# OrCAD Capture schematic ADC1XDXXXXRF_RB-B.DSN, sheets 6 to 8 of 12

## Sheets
6 Power1: size C; block B4
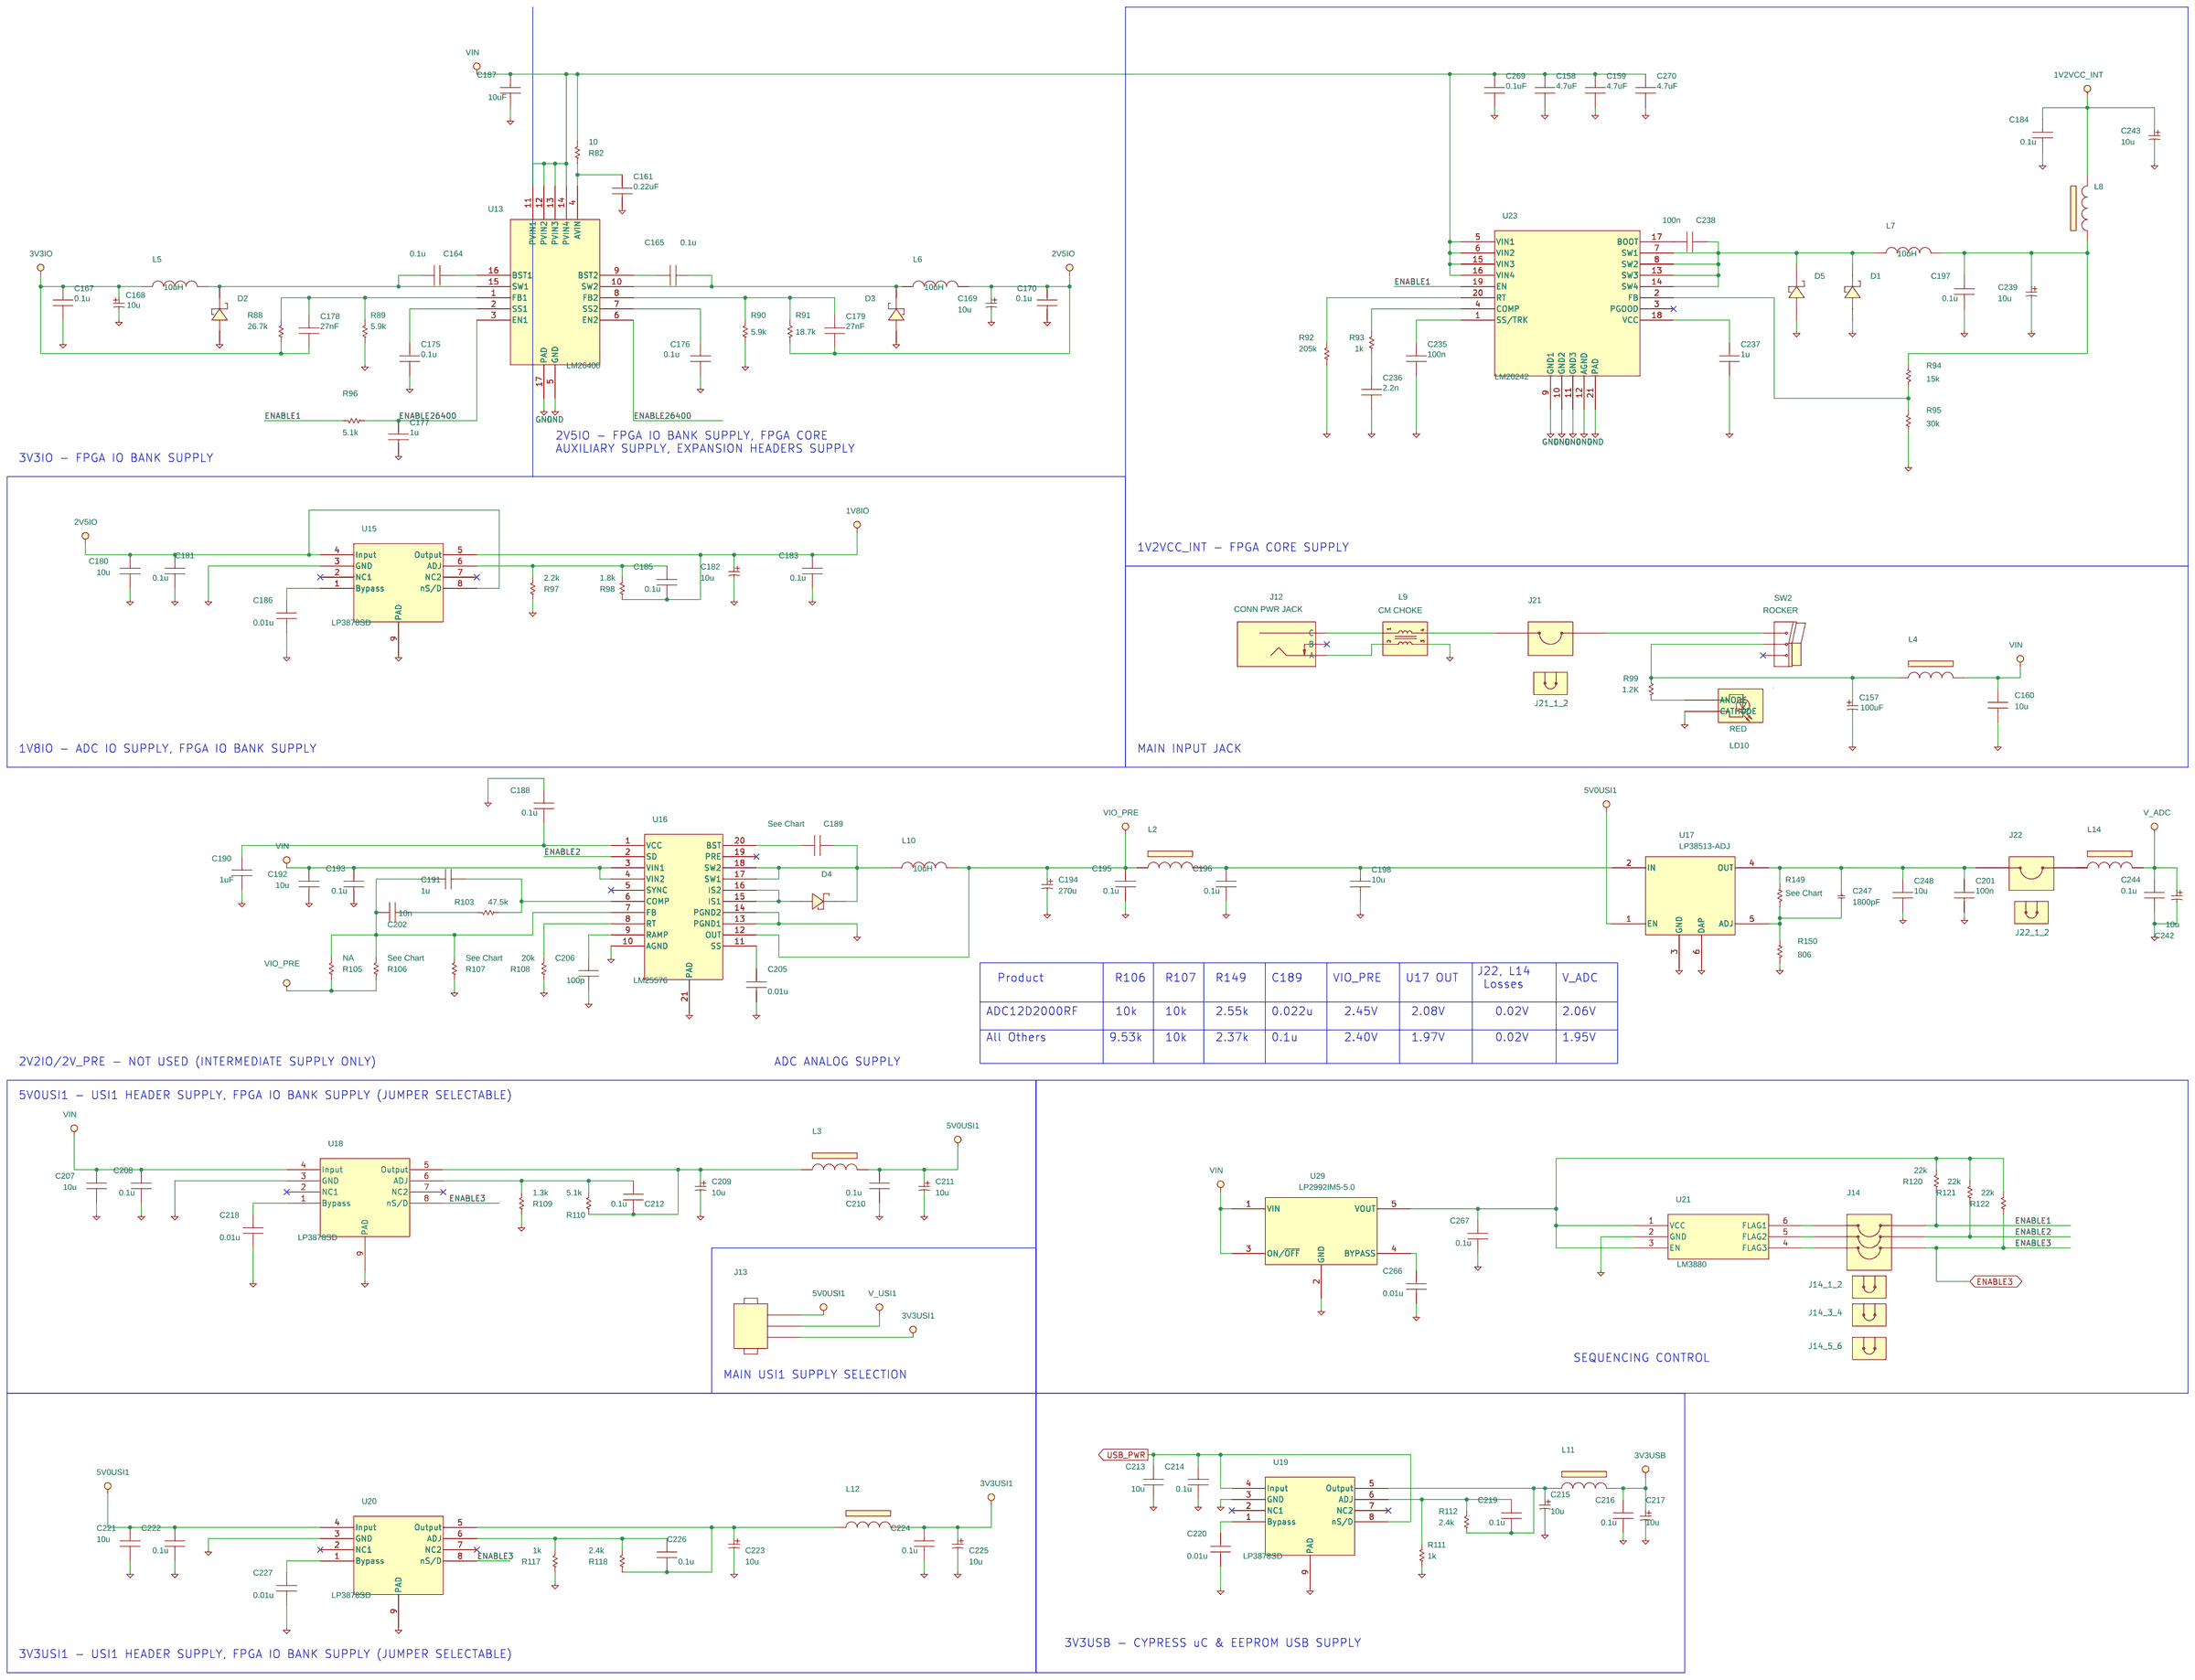
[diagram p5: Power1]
7 Power2: size C; block B4
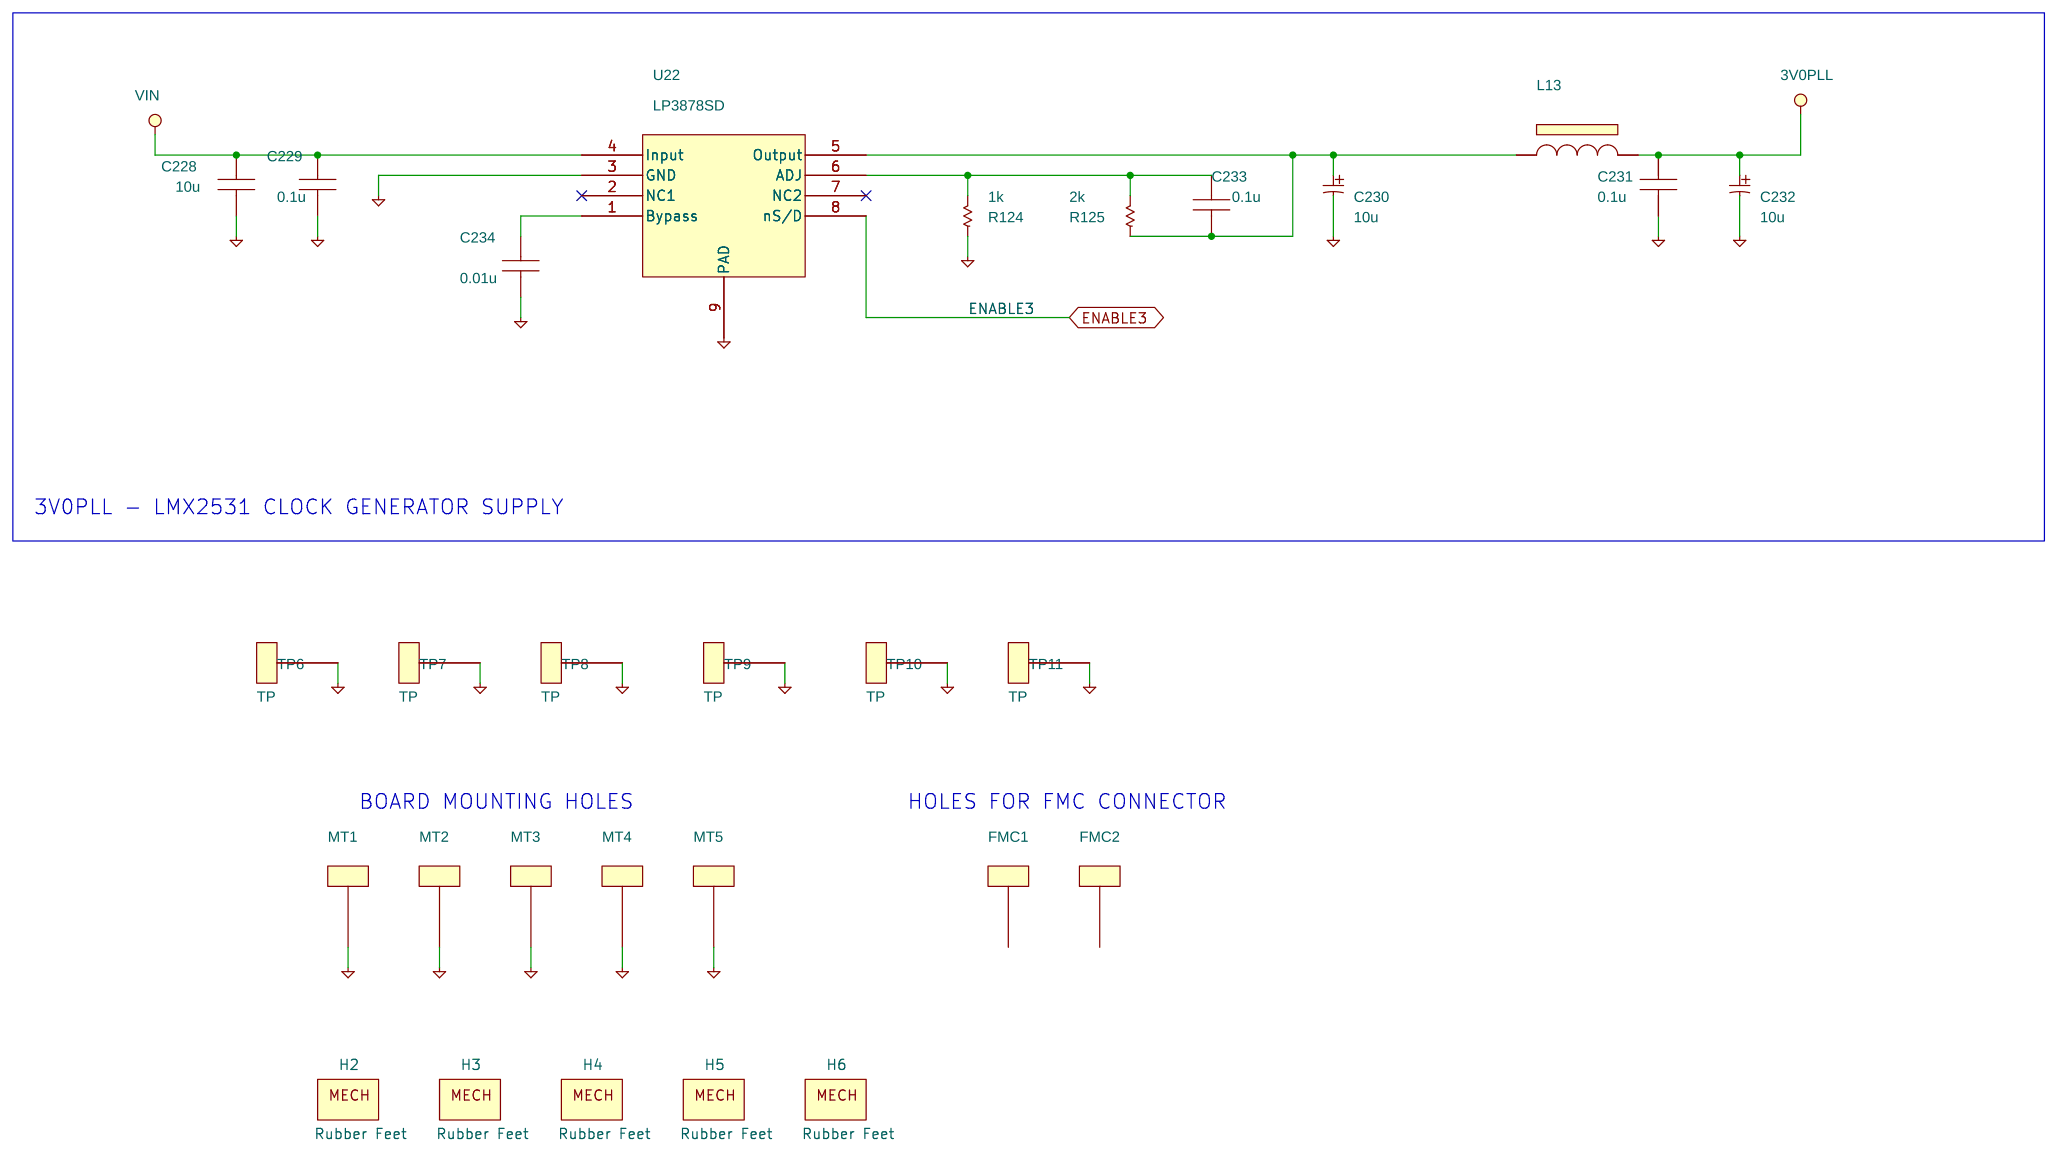
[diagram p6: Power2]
8 PLL: size C; block B3
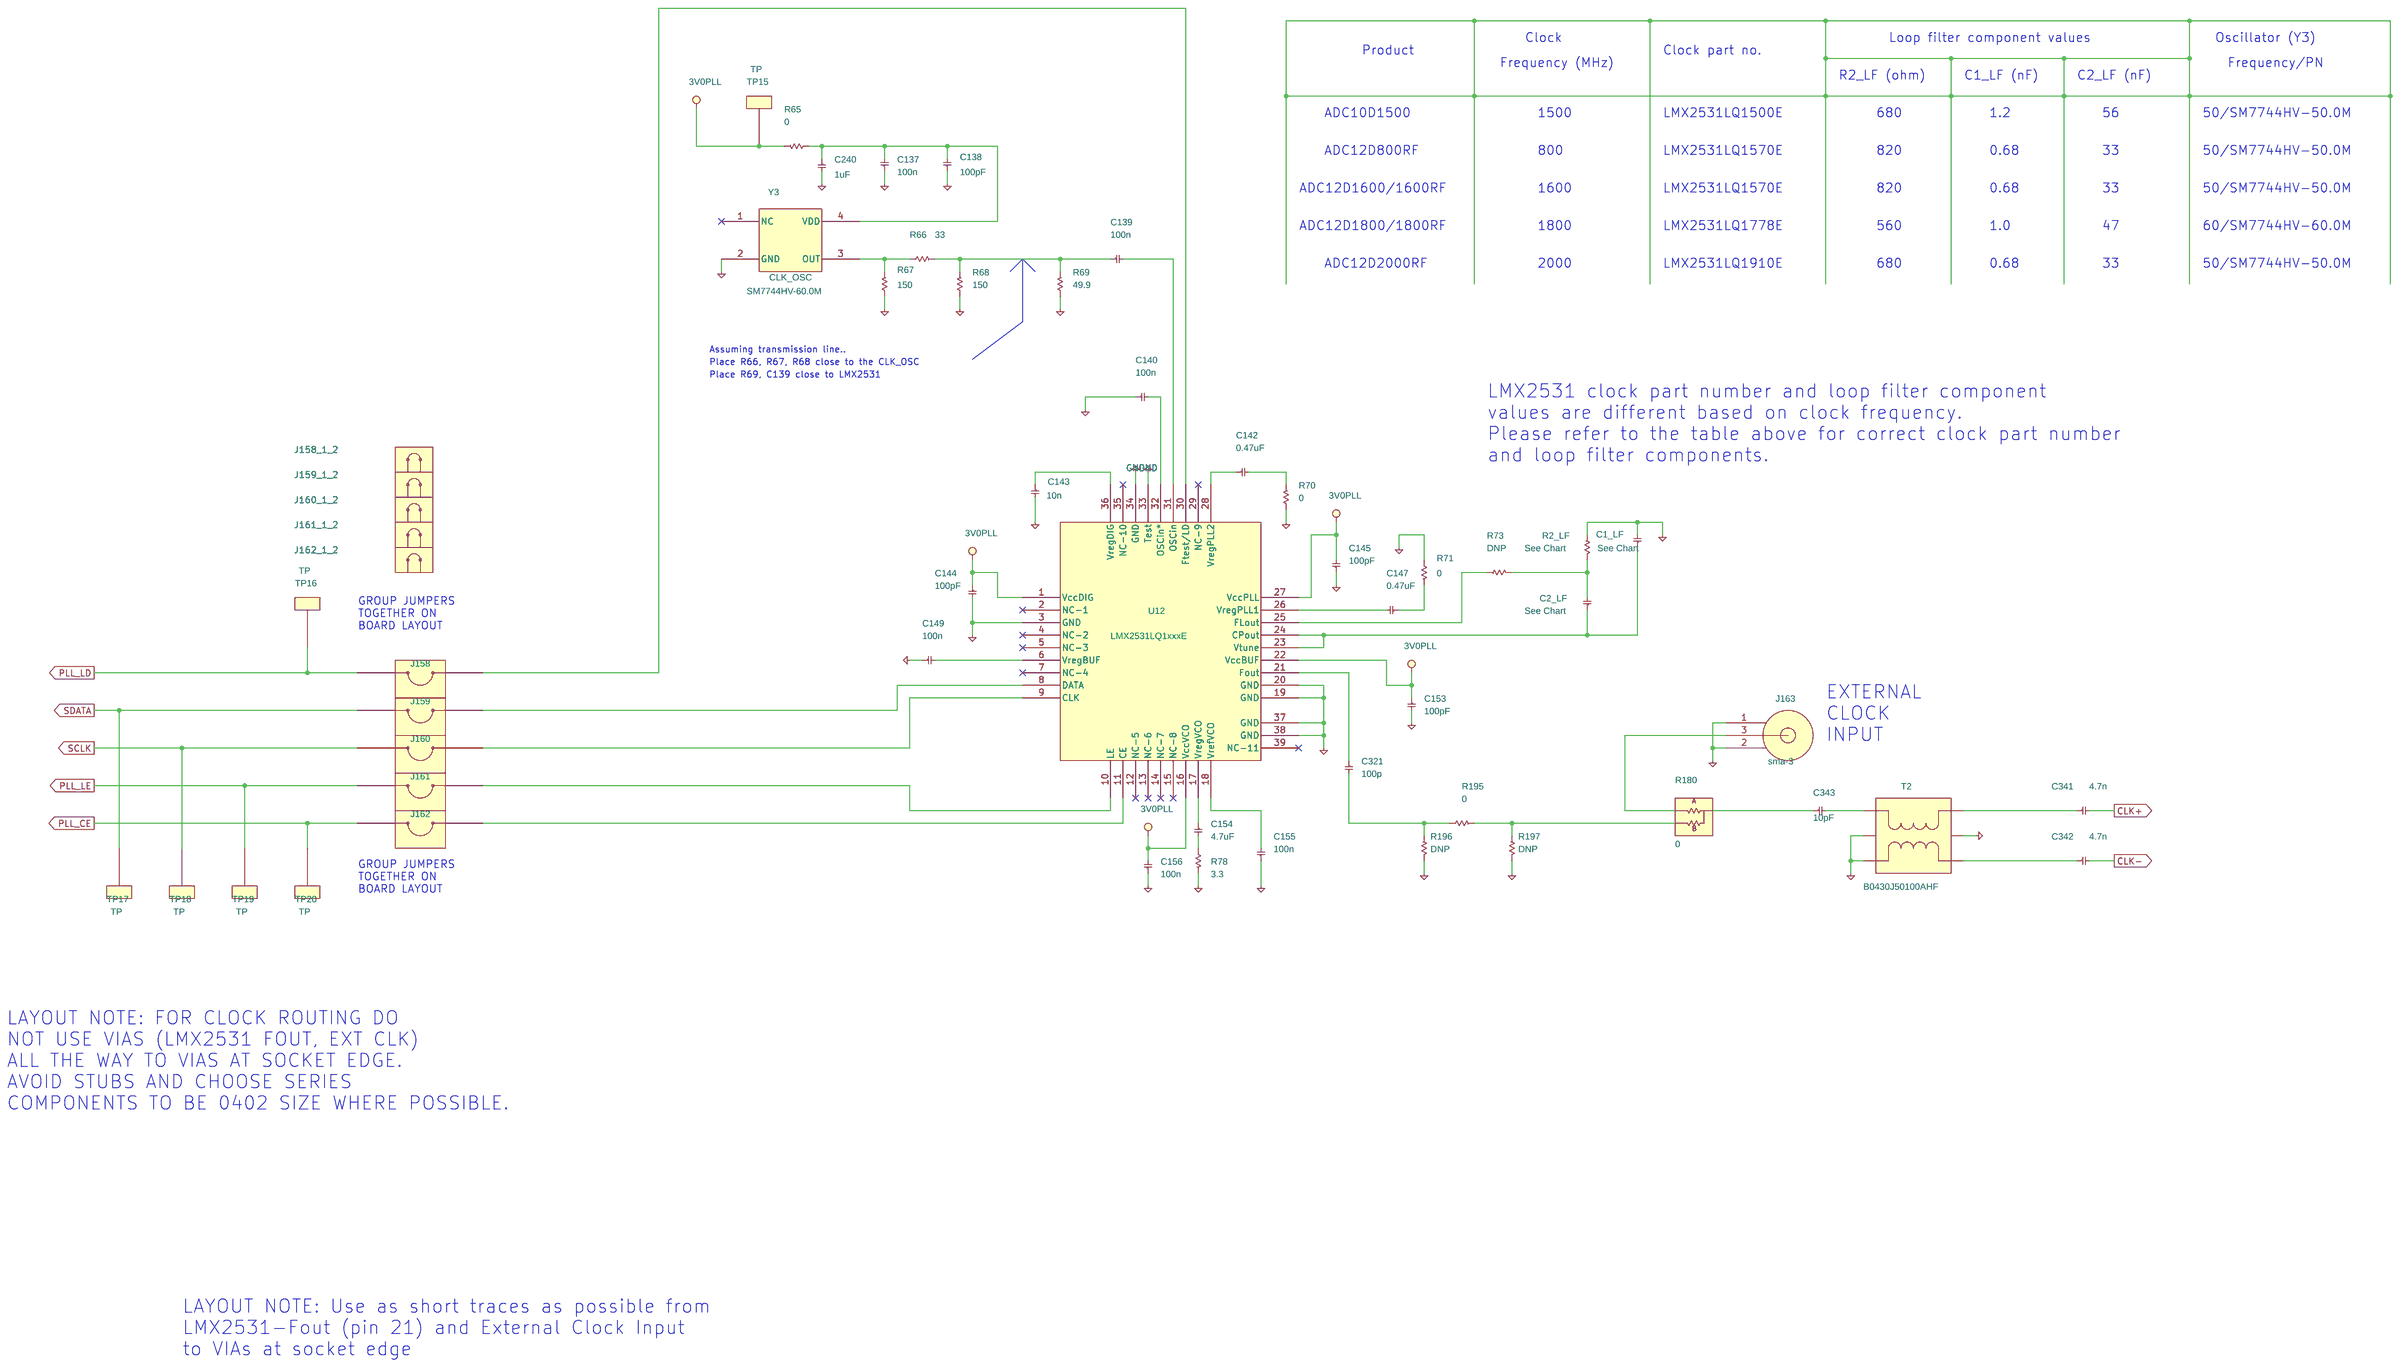
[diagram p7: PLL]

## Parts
sheet PLL
C1_LF  See Chart  [R0402_NO_SS]
C2_LF  See Chart  [c0603]
C137  100n  [c0603]
C138  100pF  [c0603]
C139  100n  [c0603]
C140  100n  [c0603]
C142  0.47uF  [c0603]
C143  10n  [c0603]
C144  100pF  [c0603]
C145  100pF  [c0603]
C147  0.47uF  [c0603]
C149  100n  [c0603]
C153  100pF  [c0603]
C154  4.7uF  [c0603]
C155  100n  [c0603]
C156  100n  [c0603]
C240  1uF  [c0603]
C321  100p  [R0402_NO_SS]
C341  4.7n  [c0402_no_ss]
C342  4.7n  [c0402_no_ss]
C343  10pF  [c0402_no_ss]
J158  JUMPER1  [blkcon_2x1]
J158_1_2  SHUNT
J159  JUMPER1  [blkcon_2x1]
J159_1_2  SHUNT
J160  JUMPER1  [blkcon_2x1]
J160_1_2  SHUNT
J161  JUMPER1  [blkcon_2x1]
J161_1_2  SHUNT
J162  JUMPER1  [blkcon_2x1]
J162_1_2  SHUNT
J163  sma-3  [RF_SMA_END_LAUNCH]
R2_LF  See Chart  [R0402_NO_SS]
R65  0  [r0603]
R66  33  [r0603]
R67  150  [r0603]
R68  150  [r0603]
R69  49.9  [r0603]
R70  0  [r0603]
R71  0  [r0603]
R73  DNP  [R0402_NO_SS]
R78  3.3  [r0603]
R180  0  [0402_TRIPAD_2_to_3]
R195  0  [R0402_NO_SS]
R196  DNP  [R0402_NO_SS]
R197  DNP  [R0402_NO_SS]
T2  B0430J50100AHF  [soic6_026_wg049_L079]
TP15  TP  [tp40]
TP16  TP  [tp40]
TP17  TP  [tp40]
TP18  TP  [tp40]
TP19  TP  [tp40]
TP20  TP  [tp40]
U12  LMX2531LQ1xxxE  [LLP39_p5mm_6X6]
Y3  CLK_OSC  [osc_100m_5x7]
sheet Power1
C157  100uF  [c6p6mmx6p6mm]
C158  4.7uF  [c1210]
C159  4.7uF  [c1210]
C160  10u  [c0805]
C161  0.22uF  [c0402]
C164  0.1u  [c0402]
C165  0.1u  [c0402]
C167  0.1u  [c0402]
C168  10u  [c0805]
C169  10u  [c0805]
C170  0.1u  [c0402]
C175  0.1u  [c0402]
C176  0.1u  [c0402]
C177  1u  [c0402]
C178  27nF  [c0402]
C179  27nF  [c0402]
C180  10u  [c0805]
C181  0.1u  [c0402]
C182  10u  [c0805]
C183  0.1u  [c0402]
C184  0.1u  [c0402]
C185  0.1u  [c0402]
C186  0.01u  [c0402]
C187  10uF  [1812]
C188  0.1u  [c0402]
C189  See Chart  [c0402]
C190  1uF  [C0603]
C191  1u  [c0402]
C192  10u  [c0805]
C193  0.1u  [c0402]
C194  270u  [c10p3mmx10p3mm]
C195  0.1u  [c0402]
C196  0.1u  [c0402]
C197  0.1u  [c0402]
C198  10u  [c0805]
C201  100n  [c0402]
C202  10n  [c0402]
C205  0.01u  [c0402]
C206  100p  [c0402]
C207  10u  [c0805]
C208  0.1u  [c0402]
C209  10u  [c0805]
C210  0.1u  [c0402]
C211  10u  [c0805]
C212  0.1u  [c0402]
C213  10u  [c0805]
C214  0.1u  [c0402]
C215  10u  [c0805]
C216  0.1u  [c0402]
C217  10u  [c0805]
C218  0.01u  [c0402]
C219  0.1u  [c0402]
C220  0.01u  [c0402]
C221  10u  [c0805]
C222  0.1u  [c0402]
C223  10u  [c0805]
C224  0.1u  [c0402]
C225  10u  [c0805]
C226  0.1u  [c0402]
C227  0.01u  [c0402]
C235  100n  [c0402]
C236  2.2n  [c0402]
C237  1u  [c0805]
C238  100n  [c0402]
C239  10u  [c0805]
C242  10u  [c0805]
C243  10u  [c0805]
C244  0.1u  [c0402]
C247  1800pF  [c0603]
C248  10u  [c0805]
C266  0.01u  [c0402]
C267  0.1u  [c0402]
C269  0.1uF  [c0805]
C270  4.7uF  [c1210]
D1  DIODE SCHOTTKY  [SOD_123_21]
D2  DIODE SCHOTTKY  [DO214_AB]
D3  DIODE SCHOTTKY  [DO214_AB]
D4  DIODE SCHOTTKY  [DO214_AB]
D5  DIODE SCHOTTKY  [SOD_123_21]
J12  CONN PWR JACK  [JACK_POWER]
J13  HEADER 3  [blkcon_3x1]
J14  JUMPER2  [blkcon_3x2]
J14_1_2  SHUNT
J14_3_4  SHUNT
J14_5_6  SHUNT
J21  JUMPER1  [blkcon_2x1]
J21_1_2  SHUNT
J22  JUMPER1  [blkcon_2x1]
J22_1_2  SHUNT
L2  INDUCTOR FERRITE/SM  [r0603]
L3  INDUCTOR FERRITE/SM  [r0603]
L4  INDUCTOR FERRITE/SM  [r0603]
L5  10uH  [EIA_481]
L6  10uH  [EIA_481]
L7  10uH  [EIA_481]
L8  INDUCTOR FERRITE/SM  [r0603]
L9  CM CHOKE  [choke_cm2545-b]
L10  10uH  [EIA_481]
L11  INDUCTOR FERRITE/SM  [r0603]
L12  INDUCTOR FERRITE/SM  [r0603]
L14  INDUCTOR FERRITE/SM  [r0603]
LD10  RED  [r1206]
R82  10  [r0603]
R88  26.7k  [r0603]
R89  5.9k  [r0603]
R90  5.9k  [r0603]
R91  18.7k  [r0603]
R92  205k  [r0603]
R93  1k  [r0603]
R94  15k  [r0603]
R95  30k  [r0603]
R96  5.1k  [r0603]
R97  2.2k  [r0603]
R98  1.8k  [r0603]
R99  1.2K  [r1206]
R103  47.5k  [r0603]
R105  NA  [r0603]
R106  See Chart  [r0603]
R107  See Chart  [r0603]
R108  20k  [r0603]
R109  1.3k  [r0603]
R110  5.1k  [r0603]
R111  1k  [r0603]
R112  2.4k  [r0603]
R117  1k  [r0603]
R118  2.4k  [r0603]
R120  22k  [r0603]
R121  22k  [r0603]
R122  22k  [r0603]
R149  See Chart  [r0603]
R150  806  [r0603]
SW2  ROCKER  [SW_TH_RA_7101]
U13  LM26400  [TSSOP16_65M_WG6P4_L5]
U15  LP3878SD  [SOIC8_050_WG244_L200_EP]
U16  LM25576  [TSSOP20_65M_WG6P4_L6P5_EP]
U17  LP38513-ADJ  [SC-MKT-TJ5A]
U18  LP3878SD  [SOIC8_050_WG244_L200_EP]
U19  LP3878SD  [SOIC8_050_WG244_L200_EP]
U20  LP3878SD  [SOIC8_050_WG244_L200_EP]
U21  LM3880  [SOT_23_6]
U23  LM20242  [TSSOP20_65M_WG6P4_L6P5_EP]
U29  LP2992IM5-5.0  [SC-MKT-MF05A]
sheet Power2
C228  10u  [c0805]
C229  0.1u  [c0402]
C230  10u  [c0805]
C231  0.1u  [c0402]
C232  10u  [c0805]
C233  0.1u  [c0402]
C234  0.01u  [c0402]
FMC1  TP  [VIA85D55]
FMC2  TP  [VIA85D55]
H2  Rubber Feet
H3  Rubber Feet
H4  Rubber Feet
H5  Rubber Feet
H6  Rubber Feet
L13  INDUCTOR FERRITE/SM  [r0603]
MT1  TP  [VIA85D55]
MT2  TP  [VIA85D55]
MT3  TP  [VIA85D55]
MT4  TP  [VIA85D55]
MT5  TP  [VIA85D55]
R124  1k  [r0603]
R125  2k  [r0603]
TP6  TP  [tp40]
TP7  TP  [tp40]
TP8  TP  [tp40]
TP9  TP  [tp40]
TP10  TP  [tp40]
TP11  TP  [tp40]
U22  LP3878SD  [SOIC8_050_WG244_L200_EP]

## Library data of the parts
C1_LF = C-NON-POL: Manufactured By: Murata; Part Number: GRM155R71H471JA01J
C2_LF = C-NON-POL: Manufactured By: Kemet; Part Number: C0603C563J4RACTU
C137 C139 C140 C149 = C-NON-POL: Capacitor, SMT 0603, MLC, X7R, 10%, 16V; Distributor: Digikey; Distributor Part Number: PCC1762TR-ND; Manufactured by: Panasonic; Manufacturer: Panasonic; Manufacturer Part Number: ECJ-1VB1C104K; Part Number: ECJ-1VB1C104K
C138 C144 C145 C153 = C-NON-POL: Capacitor, SMT 0603, MLC, NPO, 5%, 50V; Distributor: Digikey; Distributor Part Number: PCC101ACVTR-ND; Manufactured by: Panasonic; Manufacturer: Panasonic; Manufacturer Part Number: ECJ-1VC1H101J; Part Number: ECJ-1VC1H101J
C142 C147 = C-NON-POL: Capacitor, SMT 0603, MLC, X7R, 10%, 16V; Distributor: Digikey; Distributor Part Number: 399-4922-2-ND; Manufactured by: Kemet; Manufacturer: Kemet; Manufacturer Part Number: C0603C474K4RACTU; Part Number: C0603C474K4RACTU
C143 = C-NON-POL: Capacitor, SMT 0603, MLC, X7R, 10%, 16V; Distributor: Digikey; Distributor Part Number: PCC1750TR-ND; Manufactured by: Panasonic; Manufacturer: Panasonic; Manufacturer Part Number: ECJ-1VB1C103K; Part Number: ECJ-1VB1C103K
C154 = C-NON-POL: Capacitor, SMT 0603, MLC, NPO, 5%, 50V; Distributor: Digikey; Distributor Part Number: PCC101ACVTR-ND; Manufactured By: Samsung; Manufacturer: Panasonic; Manufacturer Part Number: ECJ-1VC1H101J; Part Number: CL10B475KQ8NQNC
C155 C156 = C-NON-POL: Capacitor, SMT 0603, MLC, X7R, 10%, 16V; Distributor: Digikey; Distributor Part Number: PCC1762TR-ND; Manufactured By: Panasonic; Manufacturer: Panasonic; Manufacturer Part Number: ECJ-1VB1C104K; Part Number: ECJ-1VB1C104K
C240 = C-NON-POL: Capacitor, SMT 0603, MLC, X5R, 10%, 16V; Distributor: Digikey; Distributor Part Number: PCC2224TR-ND; Manufactured by: Panasonic; Manufacturer: Panasonic; Manufacturer Part Number: ECJ-1VB1C105K; Part Number: ECJ-1VB1C105K
C321 = C-NON-POL: Distributed by: Digikey; Distributor Part #: 478-1129-1-ND; Manufactured By: AVX Corporation; Part Description: CAP CER 0.1UF 10% 10V X5R 0402; Part Number: 0402ZD104KAT2A
C341 C342 = C-NON-POL: Distributed by: Digikey; Distributor Part #: 399-1035-1-ND; Manufactured By: Kemet; Part Description: CAP 4700PF 25V CERAMIC X7R 0402; Part Number: C0402C472K3RACTU
C343 = C-NON-POL: Capacitor, SMT 0603, MLC, NPO, 5%, 50V; Distributor: Digikey; Distributor Part Number: PCC101ACVTR-ND; Manufactured by: Murata; Part Number: GRM1555C1H100FA01D
J158-J162 = JUMPER1: Distributed by: Digikey; Distributor Part #: S1012E-36-ND; Manufactured by: Sullins; Part Description: JUMPER 2X1  th_2_hdr1x2_m_str_100; Part Number: PEC36SAAN
J14_1_2 J14_3_4 J14_5_6 J21_1_2 J22_1_2 J158_1_2 J159_1_2 J160_1_2 J161_1_2 J162_1_2 = SHUNT
J163 = sma-3_0: Distributed by: Digikey or Mouser; Distributor Part #: J658-ND or 530-142-0701-851; Manufactured by: Emerson Network Power Connectivity Solutions; Part Description: CONN JACK END LAUNCH PC GOLD SMA; Part Number: 142-0701-851
R2_LF = RESISTOR: Manufactured By: Panasonic; Part Number: ERJ-2RKF8200X
R65 = RESISTOR: RES 0 OHM 1/10W 5% 0603 SMD; Distributor: Digikey; Distributor Part Number: P0.0GTR-ND; Manufactured by: Panasonic; Manufacturer: Panasonic; Manufacturer Part Number: ERJ-3GEY0R00V; Part Number: ERJ-3GEY0R00V
R66 = RESISTOR: RES 18 OHM 1/10W 5% 0603 SMD; Distributor: Digikey; Distributor Part Number: P18GTR-ND; Manufactured by: Panasonic; Manufacturer: Panasonic; Manufacturer Part Number: ERJ-3EKF33R0V; Part Number: ERJ-3GEYJ180V
R67 = RESISTOR: RES 680 OHM 1/10W 5% 0603 SMD; Distributor: Digikey; Distributor Part Number: P680GTR-ND; Manufactured by: Panasonic; Manufacturer: Panasonic; Manufacturer Part Number: ERJ-3GEYJ681V; Part Number: ERJ-3EKF1500V
R68 = RESISTOR: RES 270 OHM 1/10W 5% 0603 SMD; Distributor: Digikey; Distributor Part Number: P270GTR-ND; Manufactured by: Panasonic; Manufacturer: Panasonic; Manufacturer Part Number: ERJ-3GEYJ271V; Part Number: ERJ-3EKF1500V
R69 = RESISTOR: RES 49.9 OHM 1/10W 1% 0603 SMD; Distributor: Digikey; Distributor Part Number: P49.9HCT-ND; Manufactured by: Panasonic; Manufacturer: Panasonic; Manufacturer Part Number: ERJ-3EKF49R9V; Part Number: ERJ-3EKF49R9V
R70 R71 = RESISTOR: RES 10K OHM 1/10W 5% 0603 SMD; Distributor: Digikey; Distributor Part Number: P10KGTR-ND; Manufactured by: Panasonic; Manufacturer: Panasonic; Manufacturer Part Number: ERJ-3GEYJ103V; Part Number: ERJ-3GEY0R00V
R73 R105 = RESISTOR
R78 = RESISTOR: RES 18 OHM 1/10W 5% 0603 SMD; Distributor: Digikey; Distributor Part Number: P18GTR-ND; Manufactured By: Panasonic; Manufacturer: Panasonic; Manufacturer Part Number: ERJ-3RQF3R3V; Part Number: ERJ-3RQF3R3V
R180 = RESISTOR_TRIPAD: Distributed by: Digikey; Distributor Part #: 541-0.0JCT-ND; Manufactured by: Panasonic; Part Description: RES 0.0 OHM 1/16W 0402 SMD; Part Number: CRCW04020000Z0ED
R195 = RESISTOR: Distributed by: Digikey; Distributor Part #: P18JCT-ND; Manufactured By: Panasonic; Part Description: RES 0.0 OHM 1/10W JUMP 0402 SMD; Part Number: ERJ-2GE0R00X
R196 R197 = RESISTOR: Distributed by: Digikey; Distributor Part #: P330JCT-ND; Manufactured By: Panasonic; Part Description: RES 330 OHM 1/10W 5% 0402 SMD; Part Number: ERJ-2GEJ331X
T2 = TRANSFORMER_AIR_CORE_0: Distributed by: Anaren; Manufactured By: Anaren; Part Description: Ultra Low Profile 0805 Balun 50 ohm to 100 ohm Balanced
TP15-TP20 = TEST_POINT: Distributed by: N/A; Distributor Part #: N/A; Manufactured By: N/A; Part Number: N/A
U12 = LMX2531LQ1500E: Manufactured by: Texas Instruments
Y3 = Oscillator_4smd_0: Distributor: Pletronics; Distributor Part Number: SM7744HV-60.0M; Manufactured by: Pletronics; Manufacturer: Pletronics; Manufacturer Part Number: SM7744HV-60.0M; Part Number: SM7744HV-60.0M
C157 = C-POLARISED: Distributed by: Digikey; Distributor Part #: 565-2462-1-ND; Manufactured by: United Chemi-Con; Part Description: CAP ALUM 100UF 25V 20% SMD; Part Number: EMVY250ADA101MF80G
C158 C159 C270 = CAPACITOR_NON-POL: Distributed by: Digi-Key; Distributor Part #: 587-1373-1-ND; Manufactured by: Taiyo Yuden; Part Description: CAP CER 4.7UF 25V 10% X7R 1210; Part Number: TMK325B7475KN-T
C160 C180 C192 C207 C228 = CAPACITOR_NON-POL: Distributed by: Digi-Key; Distributor Part #: 445-5985-1-ND; Manufactured by: TDK; Part Description: CAP CER 10UF 25V 20% X5R 0805; Part Number: C2012X5R1E106M
C161 = CAPACITOR_NON-POL: Distributed by: Digikey; Distributor Part #: 445-5945-1-ND; Manufactured by: TDK Corporation; Part Description: CAP CER 0.22UF 25V 20% X5R 0402; Part Number: C1005X5R1E224M
C164 C165 C167 C170 C175 C176 C183-C185 C188 C195-C197 C210 C212 C214 C216 C219 C222 C224 C226 C231 C233 C244 C267 = CAPACITOR_NON-POL: Distributed by: Digikey; Distributor Part #: PCC2146TR-ND; Manufactured by: Panasonic; Part Description: Capacitor, SMT 0402, MLC, X5R, 10%, 10V; Part Number: ECJ-0EB1A104K
C168 C169 C182 C209 C211 C215 C217 C223 C225 C230 C232 C239 C242 C243 = C-POLARISED: Distributed by: Digikey; Distributor Part #: 445-1363-2-ND; Manufactured by: TDK; Part Description: CAP CER 10UF 6.3V 20% X5R 0805; Part Number: C2012X5R0J106M/1.25
C177 C191 = CAPACITOR_NON-POL: Distributed by: Digikey; Distributor Part #: 399-4873-1-ND; Manufactured by: Kemet; Part Description: CAP CER 1UF 6.3V 10% X5R 0402; Part Number: C0402C105K9PACTU
C178 C179 = CAPACITOR_NON-POL: Distributed by: Digikey; Distributor Part #: 478-1119-1-ND; Manufactured by: AVX Corporation; Part Description: CAP CER 0.027UF 10V 10% X7R 0402; Part Number: 0402ZC273KAT2A
C181 C193 C208 C229 = CAPACITOR_NON-POL: Distributed by: Digikey; Distributor Part #: 587-1456-1-ND; Manufactured by: Taiyo Yuden; Part Description: CAP CER 0.1UF 25V 10% X5R 0402; Part Number: TMK105BJ104KV-F
C186 C205 C218 C220 C227 C234 C266 = CAPACITOR_NON-POL: Distributed by: Digikey; Distributor Part #: 399-1038-1-ND; Manufactured by: Kemet; Part Description: CAP CER 10000PF 16V 10% X7R 0402; Part Number: C0402C103K4RACTU
C187 = CAPACITOR_NON-POL: Distributed by: Digikey; Distributor Part #: 445-3926-1-ND; Manufactured by: TDK Corporation; Part Description: CAP CER 10UF 25V 20% X5R 1812; Part Number: C4532X5R1E106M
C189 = CAPACITOR_NON-POL
C190 = CAPACITOR_NON-POL: Distributed by: Digikey; Distributor Part #: 399-3118-1-ND; Manufactured by: Kemet; Part Description: CAP CER 1UF 10V 10% X5R 0603; Part Number: C0603C105K8PACTU
C194 = C-POLARISED: Distributed by: Digikey; Distributor Part #: 565-3069-2-ND; Manufactured by: United Chemi-Con; Part Description: CAP ALUM 270UF 10V 20% SMD; Part Number: APXA100ARA271MJ80G
C198 C213 C221 C248 = CAPACITOR_NON-POL: Distributed by: Digikey; Distributor Part #: 445-1363-1-ND; Manufactured by: TDK; Part Description: CAP CER 10UF 6.3V 20% X5R 0805; Part Number: C2012X5R0J106M/1.25
C201 C235 C238 = CAPACITOR_NON-POL: Distributed by: Digikey; Distributor Part #: 478-1129-1-ND; Manufactured by: AVX Corporation; Part Description: CAP CER 0.1UF 10% 10V X5R 0402; Part Number: 0402ZD104KAT2A
C202 = CAPACITOR_NON-POL: Distributed by: Digikey; Distributor Part #: 445-1260-1-ND; Manufactured by: TDK Corporation; Part Description: CAP CER 10000PF 25V 10% X7R 0402; Part Number: C1005X7R1E103K
C206 = CAPACITOR_NON-POL: Distributed by: Digikey; Distributor Part #: 399-3194-1-ND; Manufactured by: Kemet; Part Description: CAP CER 100PF 50V 5% NP0 0402; Part Number: C0402C101J5GACTU
C236 = CAPACITOR_NON-POL: Distributed by: Digikey; Distributor Part #: 399-1033-1-ND; Manufactured by: Kemet; Part Description: CAP CER 2200PF 25V 10% X7R 0402; Part Number: C0402C222K3RACTU
C237 = CAPACITOR_NON-POL: Distributed by: Digikey; Distributor Part #: 445-1587-1-ND; Manufactured by: TDK; Part Description: CAP CER 1UF 10V 10% X5R 0805; Part Number: C2012X5R1A105K/0.85
C247 = C-NON-POL: Distributed by: Digikey; Distributor Part #: 478-1218-1-ND; Manufactured by: AVX Corporation; Part Description: CAP CERM 1800PF 10% 50V X7R 0603; Part Number: 06035C182KAT2A
C269 = CAPACITOR_NON-POL: Distributed by: Digi-Key; Distributor Part #: 399-1168-1-ND; Manufactured by: Kemet; Part Description: CAP CER 0.1UF 25V 10% X7R 0805; Part Number: C0805C104K3RACTU
D1 D5 = DIODE_SCHOTTKY: Distributed by: Digikey; Distributor Part #: MBR0540TPMSCT-ND; Manufactured by: Micro Commercial Co; Part Description: DIODE SCHOTTKY 40V 500MA SOD123; Part Number: MBR0540
D2-D4 = DIODE_SCHOTTKY: Distributed by: Digikey; Distributor Part #: MBRS320T3GOSCT-ND; Manufactured by: On Semiconductor; Part Description: DIODE SCHOTTKY 20V 4A SMC; Part Number: MBRS320T3G
J12 = CONN_PWR_JACK: Distributed by: Digikey; Distributor Part #: CP-102AH-ND; Manufactured by: CUI Inc; Part Description: CONN PWR JACK 2.1X5.5MM HIGH CUR; Part Number: PJ-102AH
J13 = HEADER_3: Comment: BROKEN TO SIZE; Distributed by: Digikey; Distributor Part #: S1012E-36-ND; Manufactured by: Sullins Connector Solutions; Part Description: CONN HEADER .100 SINGL STR 36POS; Part Number: PEC36SAAN
J14 = JUMPER3: Comment: BROKEN TO SIZE; Distributed by: Digikey; Distributor Part #: S2012E-36-ND; Manufactured by: Sullins Connector Solutions; Part Description: CONN HEADER .100 DUAL STR 72POS; Part Number: PEC36DAAN
J21 J22 = JUMPER1: Comment: BROKEN TO SIZE; Distributed by: Digikey; Distributor Part #: S1012E-36-ND; Manufactured by: Sullins Connector Solutions; Part Description: CONN HEADER .100 SINGL STR 36POS; Part Number: PEC36SAAN
L2 = INDUCTOR_FERRITE_SM: Distributed by: Digikey; Distributor Part #: 490-3996-1-ND; Manufactured by: Murata Electronics North America; Part Description: FILTER CHIP 120 OHM 3A 0603; Part Number: BLM18SG121TN1D
L3 L13 = INDUCTOR_FERRITE_SM: Distributed by: Digikey; Distributor Part #: 490-3997-1-ND; Manufactured by: Murata Electronics North America; Part Description: FILTER CHIP 330 OHM 1.5A 0603; Part Number: BLM18SG331TN1D
L4 = INDUCTOR_FERRITE_SM: Distributed by: Digi-Key; Distributor Part #: 490-3995-1-ND; Manufactured by: Murata Electronics North America; Part Description: FILTER CHIP 26 OHM 6A 0603; Part Number: BLM18SG260TN1D
L5-L7 L10 = INDUCTOR: Distributed by: Coilcraft; Distributor Part #: MSS1246-103ML; Manufactured by: Coilcraft; Part Description: 10uH 3.4A EIA_481; Part Number: MSS1246-103ML
L8 L14 = INDUCTOR_FERRITE_SM: Distributed by: Digi-Key; Distributor Part #: 490-3995-1-ND; Manufactured by: Murata Electronics North America; Part Description: FILTER CHIP 26 OHM 6A 0603; Part Number: BLM18SG260TN1
L9 = INDUCTOR_CM_CHOKE: Distributed by: Digikey; Distributor Part #: 240-2485-ND; Manufactured by: Laird-Signal Integrity Products; Part Description: CHOKE COMMON MODE 170 OHMS PCB; Part Number: CM2545X171B-10
L11 L12 = INDUCTOR_FERRITE_SM: Distributed by: Digikey; Distributor Part #: 490-3997-1-ND; Manufactured by: Murata Electronics North America; Part Description: FILTER CHIP 330 OHM 1.5A 0603; Part Number: BLM18SG331TN1
LD10 = LED_SNGLE_PANEL: Distributed by: Digikey; Distributor Part #: 67-1356-1-ND; Manufactured by: Lumex; Part Description: LED 635NM RED WTR CLR 1206 SMD; Part Number: SML-LX1206IC-TR
R82 = RESISTOR: Distributed by: Digikey; Distributor Part #: P10GCT-ND; Manufactured by: Panasonic; Part Description: RES 10 OHM 1/10W 5% 0603 SMD; Part Number: ERJ-3GEYJ100V
R88 = RESISTOR: Distributed by: Digikey; Distributor Part #: P26.7KABTR-ND; Manufactured by: Panasonic; Part Description: RES 26.7K OHM 1/10W 1% 0603 SMD; Part Number: ERJ-1GEF2672C
R89 R90 = RESISTOR: Distributed by: Digikey; Distributor Part #: 311-5.9KDTR-ND; Manufactured by: Yageo; Part Description: RES 5.9K OHM 1/10W 1% 0603 SMD; Part Number: RT0603DRD075K9L
R91 = RESISTOR: Distributed by: Digikey; Distributor Part #: P18.7KHTR-ND; Manufactured by: Panasonic; Part Description: RES 18.7K OHM 1/10W 1% 0603 SMD; Part Number: ERJ-3EKF1872V
R92 = RESISTOR: Distributed by: Digikey; Distributor Part #: P205KHCT-ND; Manufactured by: Panasonic; Part Description: RES 205K OHM 1/10W 1% 0603 SMD; Part Number: ERJ-3EKF2053V
R93 R111 R117 R124 = RESISTOR: Distributed by: Digikey; Distributor Part #: P1.0KGCT-ND; Manufactured by: Panasonic; Part Description: RES 1.0K OHM 1/10W 5% 0603 SMD; Part Number: ERJ-3GEYJ102V
R94 = RESISTOR: Distributed by: Digikey; Distributor Part #: P15KGTR-ND; Manufactured by: Panasonic; Part Description: RES 15K OHM 1/10W 5% 0603 SMD; Part Number: ERJ-3GEYJ153V
R95 = RESISTOR: Distributed by: Digikey; Distributor Part #: P30KGCT-ND; Manufactured by: Panasonic; Part Description: RES 30K OHM 1/10W 5% 0603 SMD; Part Number: ERJ-3GEYJ303V
R96 R110 = RESISTOR: Distributed by: Digikey; Distributor Part #: P5.1KGCT-ND; Manufactured by: Panasonic; Part Description: RES 5.1K OHM 1/10W 5% 0603 SMD; Part Number: ERJ-3GEYJ512V
R97 = RESISTOR: Distributed by: Digikey; Distributor Part #: P2.2KGCT-ND; Manufactured by: Panasonic; Part Description: RES 2.2K OHM 1/10W 5% 0603 SMD; Part Number: ERJ-3GEYJ222V
R98 = RESISTOR: Distributed by: Digikey; Distributor Part #: P1.8KGCT-ND; Manufactured by: Panasonic; Part Description: RES 1.8K OHM 1/10W 5% 0603 SMD; Part Number: ERJ-3GEYJ182V
R99 = RESISTOR: Distributed by: Digikey; Distributor Part #: P1.2KECT-ND; Manufactured by: Panasonic - ECG; Part Description: RES 1.2K OHM 1/4W 5% 1206 SMD; Part Number: ERJ-8GEYJ122V
R103 = RESISTOR: Distributed by: Digikey; Distributor Part #: P47.5KHCT-ND; Manufactured by: Panasonic; Part Description: RES 47.5K OHM 1/10W 1% 0603 SMD; Part Number: ERJ-3EKF4752V
R106 = RESISTOR: Manufactured by: Panasonic; Part Number: ERJ-3EKF7871V
R107 = RESISTOR: Manufactured by: Panasonic; Part Number: ERJ-3EKF1002V
R108 = RESISTOR: Distributed by: Digikey; Distributor Part #: P20.0KHCT-ND; Manufactured by: Panasonic; Part Description: RES 20.0K OHM 1/10W 1% 0603 SMD; Part Number: ERJ-3EKF2002V
R109 = RESISTOR: Distributed by: Digikey; Distributor Part #: P1.3KGCT-ND; Manufactured by: Panasonic; Part Description: RES 1.3K OHM 1/10W 5% 0603 SMD; Part Number: ERJ-3GEYJ132V
R112 R118 = RESISTOR: Distributed by: Digikey; Distributor Part #: P2.4KGCT-ND; Manufactured by: Panasonic; Part Description: RES 2.4K OHM 1/10W 5% 0603 SMD; Part Number: ERJ-3GEYJ242V
R120-R122 = RESISTOR: Distributed by: Digikey; Distributor Part #: P22KGCT-ND; Manufactured by: Panasonic; Part Description: RES 22K OHM 1/10W 5% 0402 SMD; Part Number: ERJ-3GEYJ223V
R149 = RESISTOR: Manufactured by: Panasonic; Part Number: ERJ-3EKF2321V
R150 = RESISTOR: Distributed by: Digikey; Distributor Part #: P806HCT-ND; Manufactured by: Panasonic; Part Description: RES 806 OHM 1/10W 1% 0603 SMD; Part Number: ERJ-3EKF8060V
SW2 = SW-DPST-2P: Distributed by: Digikey; Distributor Part #: CKN2005-ND; Manufactured by: ITT Industries/C&K Div; NC: 4,5; Part Description: SWITCH ROCKER SPDT HORZ ACT RA; Part Number: 7101J1AQE2
U13 = LM26400: Distributed by: Digikey; Distributor Part #: LM26400YMH-ND; Manufactured by: Texas Instruments; Part Description: IC REG BUCK DUAL 2A 16-ETSSOP; Part Number: LM26400YMH/NOPB
U15 = LP3878SD: Distributed by: Digikey; Distributor Part #: LP3878MR-ADJ-ND; Manufactured by: National Semiconductor; Part Description: IC VREG 800MA ADJ 8-PSOP; Part Number: LP3878MR-ADJ/NOPB
U16 = LM25576: Distributed by: Digikey; Distributor Part #: LM25576MHX-ND; Manufactured by: Texas Instruments; Part Description: IC BUCK SYNC ADJ 3A 20TSSOP; Part Number: LM25576MHX/NOPB
U17 = LP38513-ADJ: Distributed by: Digikey; Distributor Part #: LP38513TJ-ADJCT-ND; Manufactured by: Texas Instruments; Part Description: IC REG ULTRA LDO 3A ADJ TO263-5; Part Number: LP38513TJ-ADJ/NOPB
U18-U20 U22 = LP3878SD: Distributed by: Digikey; Distributor Part #: LP3878MR-ADJ-ND; Manufactured by: Texas Instruments; Part Description: IC VREG 800MA ADJ 8-PSOP; Part Number: LP3878MR-ADJ/NOPB
U21 = LM3880: Distributed by: Digikey; Distributor Part #: LM3880MF-1ABCT-ND; Manufactured by: Texas Instruments; Part Description: IC PWR SUPPLY SEQUENCER SOT23-6; Part Number: LM3880MF-1AB/NOPB
U23 = LM20242: Distributed by: Digikey; Distributor Part #: LM20242MH-ND; Manufactured by: Texas Instruments; Part Description: IC REG SYNC BUCK 2A 20TSSOP; Part Number: LM20242MH/NOPB
U29 = LP2992IM5-5.0: Distributed by: Digikey; Distributor Part #: LP2992IM5-5.0CT-ND; Manufactured by: Texas Instruments; Part Description: IC REG LDO MICRPWR 250MA SOT23-5; Part Number: LP2992IM5-5.0/NOPB
FMC1 FMC2 MT1-MT5 = TEST_POINT
H2-H6 = MechPart: Distributed by: Digikey; Distributor Part #: SJ5027-0-ND; Manufactured by: 3M; Part Description: BUMPON HEMISPHERE .63X.31 BLACK; Part Number: SJ-5027 (BLACK)
R125 = RESISTOR: Distributed by: Digikey; Distributor Part #: P2.37KHCT-ND; Manufactured By: Panasonic; Part Description: RES 2K OHM 1/10W 1% 0603 SMD; Part Number: ERJ-3EKF2001V
TP6-TP11 = TEST_POINT: Comment: BROKEN TO SIZE; Distributed by: Digikey; Distributor Part #: S1012E-36-ND; Manufactured by: Sullins Connector Solutions; Part Description: CONN HEADER .100 SINGL STR 36POS; Part Number: PEC36SAAN

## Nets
1V2VCC_INT: C184.1 C243.1(POS) L8.2 ; also on sheet 11
1V8IO: C182.1(POS) C183.1 C185.2 R98.1 U15.5(Output) ; also on sheet 3 10 11
2V5IO: C169.1(POS) C170.1 C179.2 C180.1 C181.1 L6.2 R91.1 U15.4(Input) U15.8(nS/D) ; also on sheet 4 10 11
3V0PLL: C144.1 C145.2 C153.1 C156.2 C231.1 C232.1(POS) L13.2 R65.1 TP15.1 U12.1(VccDIG) U12.16(VccVCO) U12.22(VccBUF) U12.27(VccPLL)
3V3IO: C167.1 C168.1(POS) C178.2 L5.1 R88.1 ; also on sheet 10 11
3V3USB: C216.1 C217.1(POS) L11.2 ; also on sheet 5
3V3USI1: C224.1 C225.1(POS) J13.3 L12.2 ; also on sheet 3 9 10
5V0USI1: C210.1 C211.1(POS) C221.1 C222.1 J13.1 L3.2 U17.1(EN) U20.4(Input)
GND: C1_LF.2 C137.1 C138.1 C140.1 C143.2 C144.2 C145.1 C149.1 C153.2 C155.1 C156.1 C157.2(NEG) C158.2 C159.2 C160.2 C161.2 C167.2 C168.2(NEG) C169.2(NEG) C170.2 C175.2 C176.2 C177.2 C180.2 C181.2 C182.2(NEG) C183.2 C184.2 C186.2 C187.2 C188.1 C190.2 C192.2 C193.2 C194.2(NEG) C195.2 C196.2 C197.2 C198.2 C201.2 C205.2 C206.2 C207.2 C208.2 C209.2(NEG) C210.2 C211.2(NEG) C213.2 C214.2 C215.2(NEG) C216.2 C217.2(NEG) C218.2 C220.2 C221.2 C222.2 C223.2(NEG) C224.2 C225.2(NEG) C227.2 C228.2 C229.2 C230.2(NEG) C231.2 C232.2(NEG) C234.2 C235.2 C236.2 C237.2 C239.2(NEG) C240.2 C242.2(NEG) C243.2(NEG) C244.2 C248.2 C266.2 C267.2 C269.2 C270.2 D1.1(ANODE) D2.1(ANODE) D3.1(ANODE) D5.1(ANODE) J163.1 J163.2 L9.3 LD10.2(CATHODE) MT1.1 MT2.1 MT3.1 MT4.1 MT5.1 R2_LF.1 R67.2 R68.2 R69.2 R70.2 R71.2 R78.1 R89.1 R90.1 R92.1 R95.1 R97.1 R107.1 R108.1 R109.1 R111.1 R117.1 R124.1 R150.2 R196.2 R197.2 T2.1 T2.3 T2.5 TP6.1 TP7.1 TP8.1 TP9.1 TP10.1 TP11.1 U12.3(GND) U12.19(GND) U12.20(GND) U12.33(Test) U12.34(GND) U12.37(GND) U12.38(GND) U13.5(GND) U13.17(PAD) U15.3(GND) U15.9(PAD) U16.10(AGND) U16.13(PGND1) U16.14(PGND2) U16.21(PAD) U17.3(GND) U17.6(DAP) U18.3(GND) U18.9(PAD) U19.3(GND) U19.9(PAD) U20.3(GND) U20.9(PAD) U21.2(GND) U22.3(GND) U22.9(PAD) U23.9(GND1) U23.10(GND2) U23.11(GND3) U23.12(AGND) U23.21(PAD) U29.2(GND) Y3.2(GND) ; also on sheet 3 4 5 9 10 11 12
VIN: C158.1 C159.1 C160.1 C187.1 C192.1 C193.1 C207.1 C208.1 C228.1 C229.1 C269.1 C270.1 L4.2 R82.2 U13.11(PVIN1) U13.12(PVIN2) U13.13(PVIN3) U13.14(PVIN4) U16.3(VIN1) U16.4(VIN2) U18.4(Input) U22.4(Input) U23.5(VIN1) U23.6(VIN2) U23.15(VIN3) U23.16(VIN4) U29.1(VIN) U29.3(ON/~{OFF})
B4/ENABLE1: J14.2 R96.2 R120.1 U23.19(EN)
B4/ENABLE2: J14.4 R121.1 U16.2(SD)
B4/ENABLE3: J14.6 R122.1 U18.8(nS/D) U20.8(nS/D) U22.8(nS/D)
B4/ENABLE26400: C177.1 R96.1 U13.3(EN1) U13.6(EN2)
CLK+: C341.2 ; also on sheet 3
CLK-: C342.2 ; also on sheet 3
PLL_CE: J162.1 TP20.1 ; also on sheet 9
PLL_LD: J158.1 TP16.1 ; also on sheet 9
PLL_LE: J161.1 TP19.1 ; also on sheet 9
PLL_SCLK: J160.1 TP18.1 ; also on sheet 9
PLL_SDATA: J159.1 TP17.1 ; also on sheet 9
USB_PWR: C213.1 C214.1 U19.4(Input) U19.8(nS/D) ; also on sheet 5
V_ADC: C242.1(POS) C244.1 L14.2 ; also on sheet 3 9 11
V_USI1: J13.2 ; also on sheet 10
VIO_PRE: C194.1(POS) C195.1 L2.1 L10.2 R105.1 R106.1 U16.12(OUT)
B3/N16864683: J163.3 R180.1
B3/N16864708: C342.1 T2.4
B3/N16864710: C341.1 T2.6
B3/N16864734: C343.1 R180.2
B3/N16865152: J158.2 U12.30(Ftest/LD)
B3/N16865229: J161.2 U12.10(LE)
B3/N16865231: J160.2 U12.9(CLK)
B3/N16865233: J159.2 U12.8(DATA)
B3/N16865299: J162.2 U12.11(CE)
B3/N16865342: C1_LF.1 C2_LF.1 U12.23(Vtune) U12.24(CPout)
B3/N16865346: C2_LF.2 R2_LF.2 R73.2
B3/N16865780: C321.2 R195.2 R196.1
B3/N16865782: R180.3 R195.1 R197.1
B3/N16906306: C139.1 R66.1 R68.1 R69.1
B3/N16906312: C139.2 U12.31(OSCin)
B3/N16911166: C154.1 U12.17(VregVCO)
B3/N16911176: C321.1 U12.21(Fout)
B3/N16911178: C154.2 R78.2
B3/N16911299: C155.2 U12.18(VrefVCO)
B3/N16911375: C142.2 R70.1
B3/N16911379: C142.1 U12.28(VregPLL2)
B3/N16911437: C143.1 U12.36(VregDIG)
B3/N16911467: C140.2 U12.32(OSCin*)
B3/N16911489: C149.2 U12.6(VregBUF)
B3/N16911507: C147.2 U12.26(VregPLL1)
B3/N16911511: C147.1 R71.1
B3/N16915933: C137.2 C138.2 C240.1 R65.2 Y3.4(VDD)
B3/N16915941: R66.2 R67.1 Y3.3(OUT)
B3/N16917380: R73.1 U12.25(FLout)
B3/N16922604: C343.2 T2.2
B4/N16769321: C164.1 D2.2(CATHODE) L5.2 U13.15(SW1)
B4/N16769692: C175.1 U13.2(SS1)
B4/N16769839: C178.1 R88.2 R89.2 U13.1(FB1)
B4/N16770680: C164.2 U13.16(BST1)
B4/N16772680: C161.1 R82.1 U13.4(AVIN)
B4/N16798185: C188.2 C190.1 U16.1(VCC)
B4/N16803121: C191.2 R103.1 U16.6(COMP)
B4/N16805297: C191.1 C202.1 R105.2 R106.2 R107.2 U16.7(FB)
B4/N16807514: C202.2 R103.2
B4/N16809137: R108.2 U16.8(RT)
B4/N16815468: C206.1 U16.9(RAMP)
B4/N16819191: C189.1 U16.20(BST)
B4/N16819385: C189.2 D4.2(CATHODE) L10.1 U16.17(SW1) U16.18(SW2)
B4/N16821177: D4.1(ANODE) U16.15(IS1) U16.16(IS2)
B4/N16824930: C205.1 U16.11(SS)
B4/N16831687: C196.1 C198.1 L2.2 U17.2(IN)
B4/N16860475: C218.1 U18.1(Bypass)
B4/N16862731: C212.1 R109.2 R110.2 U18.6(ADJ)
B4/N16862763: C209.1(POS) C212.2 L3.1 R110.1 U18.5(Output)
B4/N16907733: C165.1 D3.2(CATHODE) L6.1 U13.10(SW2)
B4/N16907748: C176.1 U13.7(SS2)
B4/N16907762: C179.1 R90.2 R91.2 U13.8(FB2)
B4/N16907804: C165.2 U13.9(BST2)
B4/N16954745: C223.1(POS) C226.2 L12.1 R118.1 U20.5(Output)
B4/N16954757: C227.1 U20.1(Bypass)
B4/N16954773: C226.1 R117.2 R118.2 U20.6(ADJ)
B4/N17209995: J12.2(A) L9.2
B4/N17221364: C157.1(POS) L4.1 R99.2 SW2.2
B4/N17247885: LD10.1(ANODE) R99.1
B4/N17271500: C186.1 U15.1(Bypass)
B4/N17271514: C185.1 R97.2 R98.2 U15.6(ADJ)
B4/N17272516: C230.1(POS) C233.2 L13.1 R125.1 U22.5(Output)
B4/N17272520: C234.1 U22.1(Bypass)
B4/N17272540: C233.1 R124.2 R125.2 U22.6(ADJ)
B4/N17400918: R92.2 U23.20(RT)
B4/N17401691: R93.2 U23.4(COMP)
B4/N17402468: C235.1 U23.1(SS/TRK)
B4/N17411980: C236.1 R93.1
B4/N17421515: C237.1 U23.18(VCC)
B4/N17425568: R94.2 R95.2 U23.2(FB)
B4/N17434478: C238.2 D1.2(CATHODE) D5.2(CATHODE) L7.1 U23.7(SW1) U23.8(SW2) U23.13(SW3) U23.14(SW4)
B4/N17462336: C197.1 C239.1(POS) L7.2 L8.1 R94.1
B4/N17751700: J21.1 L9.4
B4/N17752133: J21.2 SW2.3
B4/N17824195: J12.1(C) L9.1
B4/N18005197: J22.2 L14.1
B4/N18106734: C201.1 C247.1 C248.1 J22.1 R149.1 U17.4(OUT)
B4/N18113304: C247.2 R149.2 R150.1 U17.5(ADJ)
B4/N18167238: C215.1(POS) C219.2 L11.1 R112.1 U19.5(Output)
B4/N18167362: C220.1 U19.1(Bypass)
B4/N18167368: C219.1 R111.2 R112.2 U19.6(ADJ)
B4/N18175634: C267.1 R120.2 R121.2 R122.2 U21.1(VCC) U21.3(EN) U29.5(VOUT)
B4/N18175719: J14.1 U21.6(FLAG1)
B4/N18175721: J14.3 U21.5(FLAG2)
B4/N18175723: J14.5 U21.4(FLAG3)
B4/N18175776: C266.1 U29.4(BYPASS)
N18281435: C238.1 U23.17(BOOT)

Not connected (* = marked no-connect by the designer): FMC1 1; FMC2 1; J12 3(B)*; SW2 1*; U12 2(NC-1)* 4(NC-2)* 5(NC-3)* 7(NC-4)* 12(NC-5)* 13(NC-6)* 14(NC-7)* 15(NC-8)* 29(NC-9)* 35(NC-10)* 39(NC-11)*; U15 2(NC1)* 7(NC2)*; U16 5(SYNC)* 19(PRE)*; U18 2(NC1)* 7(NC2)*; U19 2(NC1)* 7(NC2)*; U20 2(NC1)* 7(NC2)*; U22 2(NC1)* 7(NC2)*; U23 3(PGOOD)*; Y3 1(NC)*

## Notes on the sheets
sheet 6
- 2V5IO - FPGA IO BANK SUPPLY, FPGA CORE
  AUXILIARY SUPPLY, EXPANSION HEADERS SUPPLY
- 3V3IO - FPGA IO BANK SUPPLY
- 1V2VCC_INT - FPGA CORE SUPPLY
- 1V8IO - ADC IO SUPPLY, FPGA IO BANK SUPPLY
- MAIN INPUT JACK
- Product
- R106
- R107
- R149
- C189
- VIO_PRE
- U17 OUT
- J22, L14
   Losses
- V_ADC
- ADC12D2000RF
  All Others
- 10k
  9.53k
- 10k
  10k
- 2.55k
  2.37k
- 0.022u
  0.1u
- 2.45V
  2.40V
- 2.08V
  1.97V
- 0.02V
  0.02V
- 2.06V
  1.95V
- 2V2IO/2V_PRE - NOT USED (INTERMEDIATE SUPPLY ONLY)
- ADC ANALOG SUPPLY
- 5V0USI1 - USI1 HEADER SUPPLY, FPGA IO BANK SUPPLY (JUMPER SELECTABLE)
- SEQUENCING CONTROL
- MAIN USI1 SUPPLY SELECTION
- 3V3USB - CYPRESS uC & EEPROM USB SUPPLY
- 3V3USI1 - USI1 HEADER SUPPLY, FPGA IO BANK SUPPLY (JUMPER SELECTABLE)
sheet 7
- 3V0PLL - LMX2531 CLOCK GENERATOR SUPPLY
- BOARD MOUNTING HOLES
- HOLES FOR FMC CONNECTOR
sheet 8
- Product
- Clock
- Clock part no.
- Loop filter component values
- Oscillator (Y3)
- Frequency (MHz)
- Frequency/PN
- R2_LF (ohm)
- C1_LF (nF)
- C2_LF (nF)
- ADC10D1500
- 1500
- LMX2531LQ1500E
- 680
- 1.2
- 56
- 50/SM7744HV-50.0M
- ADC12D800RF
- 800
- LMX2531LQ1570E
- 820
- 0.68
- 33
- 50/SM7744HV-50.0M
- ADC12D1600/1600RF
- 1600
- LMX2531LQ1570E
- 820
- 0.68
- 33
- 50/SM7744HV-50.0M
- ADC12D1800/1800RF
- 1800
- LMX2531LQ1778E
- 560
- 1.0
- 47
- 60/SM7744HV-60.0M
- ADC12D2000RF
- 2000
- LMX2531LQ1910E
- 680
- 0.68
- 33
- 50/SM7744HV-50.0M
- Assuming transmission line..
- Place R66, R67, R68 close to the CLK_OSC
- Place R69, C139 close to LMX2531
- LMX2531 clock part number and loop filter component
  values are different based on clock frequency.
  Please refer to the table above for correct clock part number
  and loop filter components.
- GROUP JUMPERS
  TOGETHER ON
  BOARD LAYOUT
- EXTERNAL
  CLOCK
  INPUT
- GROUP JUMPERS
  TOGETHER ON
  BOARD LAYOUT
- LAYOUT NOTE: FOR CLOCK ROUTING DO
  NOT USE VIAS (LMX2531 FOUT, EXT CLK)
  ALL THE WAY TO VIAS AT SOCKET EDGE.
  AVOID STUBS AND CHOOSE SERIES
  COMPONENTS TO BE 0402 SIZE WHERE POSSIBLE.
- LAYOUT NOTE: Use as short traces as possible from
  LMX2531-Fout (pin 21) and External Clock Input
  to VIAs at socket edge
